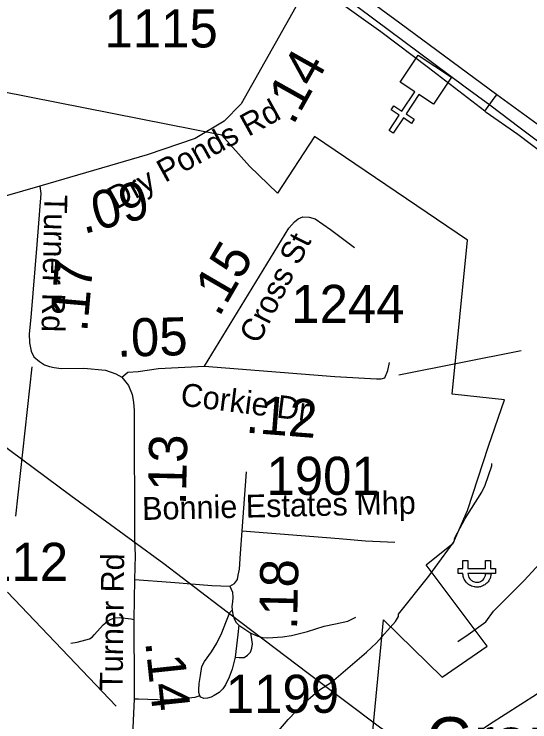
# Model space of a CAD drawing. Extents: x 1159738 to 1321356, y 736314 to 882035.
# Drawn here: x 1273311 to 1275002, y 755538 to 757861 of the extents above; entities that cross this region are included whole.
import ezdxf

# ---------------------------------------------------------------- set-up
doc = ezdxf.new("R2010")
doc.units = 0
for name, color, linetype in [('Exist Boundary Political City Limit New', 7, 'Continuous'), ('Exist Cultural Church CELL', 7, 'Continuous'), ('Exist Cultural Educational Facility Middle Label', 7, 'Continuous'), ('Exist Hydrographic Misc Water Feature', 7, 'Continuous'), ('Exist Railroad Mainline', 7, 'Continuous'), ('Exist Road Non-System Type 51', 7, 'Continuous'), ('Exist Road Primary US Attributed', 7, 'Continuous'), ('Exist Road Secondary Mileage Hundredths English Label', 7, 'Continuous'), ('Exist Road Secondary Type 51 Attributed', 7, 'Continuous'), ('Exist Road Secondary Type 51 Label', 7, 'Continuous'), ('Exist Road Secondary Type 51 Number Label', 7, 'Continuous'), ('Exist Utilities Electrical Power Substation CELL', 7, 'Continuous'), ('Exist Utilities Electrical Transmission Line', 7, 'Continuous'), ('Map Preparation Boundary City Limit Buffer Line', 7, 'Continuous')]:
    doc.layers.add(name, color=color, linetype=linetype)

msp = doc.modelspace()

# ---------------------------------------------------------------- linework, layer by layer
at = {"layer": 'Exist Boundary Political City Limit New'}
msp.add_lwpolyline([(1274481.5, 755451.1), (1274521.9, 755872.3), (1274714.5, 755684.3), (1274861.9, 755786.6), (1274662.2, 756053.1), (1274750.1, 756124.5), (1274797.7, 756231.5), (1274866.6, 756443.3), (1274918.8, 756594.5), (1274747.6, 756613.5), (1274797.5, 757119.5), (1274295.9, 757459.2), (1274174.6, 757273.7), (1274081.9, 757361.7), (1273991.5, 757464), (1272010.1, 757855.7), (1271901.3, 756992.7), (1271608.9, 756928.5)], dxfattribs=at)
at = {"layer": 'Exist Cultural Church CELL'}
msp.add_lwpolyline([(1274685.5, 757565.3), (1274638.1, 757596.8), (1274595.9, 757533.4), (1274622.5, 757515.7), (1274613.6, 757502.4), (1274587, 757520.2), (1274553.7, 757470.1), (1274540.3, 757479), (1274573.7, 757529), (1274547, 757546.8), (1274555.9, 757560.1), (1274582.5, 757542.3), (1274624.7, 757605.7), (1274576.8, 757637.8), (1274635.8, 757726.4), (1274744.5, 757653.9)], close=True, dxfattribs=at)
at = {"layer": 'Exist Hydrographic Misc Water Feature'}
msp.add_lwpolyline([(1274160, 755487.2), (1274209.6, 755545.7), (1274261.4, 755600.2), (1274312.4, 755642.8), (1274351.1, 755667.6), (1274465.9, 755766.3), (1274498.8, 755797.4), (1274560.7, 755867.6), (1274571.1, 755883.3), (1274571.4, 755891.3), (1274670.8, 756016.4), (1274754.1, 756130), (1274756.3, 756141.9), (1274790.1, 756204.9), (1274844.5, 756291.3), (1274855.1, 756315), (1274877, 756378.4), (1274877.2, 756386.4)], dxfattribs=at)
at = {"layer": 'Exist Railroad Mainline'}
msp.add_lwpolyline([(1274294.4, 757992.5), (1274438.5, 757884.3), (1274790.1, 757622.8), (1274871.1, 757562.9), (1274970.6, 757488.2), (1275188, 757324.4), (1275269.6, 757254.7), (1275292.8, 757232.4), (1275355.1, 757167.3), (1275403.2, 757109.9), (1275501.1, 756981.4), (1275557.5, 756901.1), (1275681.6, 756727.1), (1275714.9, 756681.2), (1275850.1, 756492.2), (1275904.4, 756420.6), (1275980.5, 756327.1), (1276054.8, 756250.5), (1276184.8, 756127.4), (1276521.9, 755816.4), (1276790.7, 755569.6), (1276845, 755519), (1276964.6, 755410.8), (1277036.9, 755353.2)], dxfattribs=at)
at = {"layer": 'Exist Road Non-System Type 51'}
msp.add_line((1274058.7, 756165.2), (1274072.7, 756358.9), dxfattribs=at)
for points in [[(1274853.8, 757542.1), (1274797.7, 757585.8), (1274669, 757685.1), (1274513.3, 757803.3), (1274361.3, 757912.7), (1274317.1, 757944.4), (1274278.1, 757964.1)], [(1274853.8, 757542.1), (1274884.9, 757585.2), (1274893.5, 757596.4)], [(1275260.7, 757232.9), (1275240.2, 757250.6), (1275173.1, 757305.8), (1275105.5, 757357.6), (1274962.7, 757466), (1274859.1, 757538.5), (1274853.8, 757542.1)], [(1274766, 755801.6), (1274800, 755824.2), (1274857.3, 755866.5), (1274882.9, 755900.7), (1274916.1, 755935.4), (1274982.9, 756002.2), (1275136.6, 756168.5), (1275298.2, 756346.1), (1275320.4, 756367.1)], [(1274728.2, 755416), (1274734.9, 755430.7), (1274754, 755452.5), (1274869.3, 755530.5), (1275024, 755628.6), (1275238.1, 755773.7), (1275494.7, 755942.8), (1275687.2, 756063.6), (1275875.4, 756171.8), (1275986.2, 756236.7), (1276007.1, 756250.1), (1276017.4, 756259.4)], [(1274018.3, 755983.6), (1274026.4, 755963.4), (1274027.6, 755945.5), (1274026.4, 755932.2), (1274024.7, 755916), (1274025.3, 755905)], [(1273919.5, 755623.7), (1273916.7, 755634.7), (1273916.1, 755642.8), (1273917.8, 755664.2), (1273921.3, 755690.2), (1273925.9, 755719.7), (1273934.6, 755735.9), (1273957.7, 755767.7), (1273975, 755796), (1273991.2, 755830.1), (1274004.5, 755864.2), (1274017.8, 755897), (1274025.3, 755905)], [(1274025.3, 755905), (1274027.6, 755890.5), (1274031.6, 755877.2), (1274038, 755865.1), (1274047.2, 755855.3)], [(1273496, 755795.7), (1273517.7, 755799), (1273545.3, 755807.6), (1273557.7, 755810.9), (1273566.9, 755816.3), (1273574, 755824.4), (1273602.1, 755856.4), (1273616.2, 755868.3), (1273626.5, 755873.7), (1273640, 755879.1), (1273656.3, 755880.2), (1273694.2, 755875.9), (1273702.8, 755873.7)], [(1274086.5, 755828.7), (1274109.6, 755818.8), (1274124.6, 755814.8), (1274142, 755813.1), (1274190.5, 755816.5), (1274220.5, 755821.2), (1274272.5, 755834.5), (1274326.9, 755851.8), (1274365, 755859.3), (1274405.2, 755868), (1274430.7, 755881.3)], [(1274047.2, 755855.3), (1274043.8, 755824.3), (1274035.7, 755750.3)], [(1274047.2, 755855.3), (1274086.5, 755828.7)], [(1274035.7, 755750.3), (1274049, 755748.6), (1274064.6, 755748.6), (1274075.6, 755756.7), (1274085.4, 755766.5), (1274090, 755779.8), (1274091.7, 755793.7), (1274090, 755808.1), (1274086.5, 755828.7)], [(1274035.7, 755750.3), (1274025.3, 755710.4), (1274016, 755684.4), (1274003.9, 755659.5), (1273994.7, 755646.2), (1273983.1, 755634.7), (1273966.9, 755624.3), (1273956.5, 755618.5), (1273944.4, 755615.6), (1273932.8, 755615), (1273923, 755619.1), (1273919.5, 755623.7)], [(1273919.5, 755623.7), (1273902.9, 755617.4), (1273883.2, 755615.1), (1273859.5, 755613.4), (1273811, 755609.3), (1273718.1, 755612.8), (1273704.2, 755612.8)]]:
    msp.add_lwpolyline(points, dxfattribs=at)
at = {"layer": 'Exist Road Primary US Attributed'}
msp.add_lwpolyline([(1276194.4, 756154.4), (1276086.7, 756255.2), (1276045.1, 756298.6), (1275980, 756377), (1275882, 756511.2), (1275825.3, 756588), (1275745.1, 756702.9), (1275697.5, 756764.8), (1275551.9, 756965.3), (1275457.1, 757095.9), (1275376.5, 757201.6), (1275337.2, 757247.9), (1275283.1, 757302.9), (1275224.5, 757353.2), (1275113.7, 757436.5), (1275038.1, 757490.6), (1274893.5, 757596.4), (1274575.7, 757831.2), (1274375.6, 757978.8), (1274315.6, 758022.3)], dxfattribs=at)
at = {"layer": 'Exist Road Secondary Type 51 Attributed'}
for points in [[(1274294.4, 757992.5), (1274278.1, 757964.1), (1274055.2, 757566), (1273999.1, 757509.8), (1273903.9, 757452.3), (1273746.3, 757398.8), (1273395.1, 757296.1)], [(1273395.1, 757296.1), (1273068.4, 757202.1), (1272948.9, 757166.8)], [(1273395.1, 757296.1), (1273398.4, 757271.7), (1273385, 757104.6), (1273365, 756865.2), (1273360.1, 756811.5), (1273360.5, 756782.1), (1273365.9, 756754.9), (1273375.2, 756735.7), (1273393.5, 756720.6), (1273410.4, 756709.9), (1273426, 756704.1), (1273441.5, 756700.6), (1273465.1, 756697.8), (1273539.4, 756698.4), (1273609.8, 756692.2), (1273644.1, 756680.1), (1273664.1, 756669.4)], [(1273934.7, 756704.9), (1274211.2, 757158.2), (1274229.8, 757178.8), (1274242.3, 757189.4), (1274257.6, 757195.6), (1274277.7, 757194.6), (1274297.4, 757189.4), (1274348.6, 757154.4), (1274426.9, 757095)], [(1273934.7, 756704.9), (1274362.1, 756671.1), (1274499.1, 756663.5), (1274514, 756664.2), (1274526.6, 756667.3), (1274536, 756691.1), (1274541.4, 756717.5)], [(1273664.1, 756669.4), (1273683.3, 756685.6), (1273716.9, 756688.4), (1273784.1, 756697.7), (1273934.7, 756704.9)], [(1273664.1, 756669.4), (1273685.8, 756641.5), (1273697.9, 756612.5), (1273701.9, 756587.1), (1273704.5, 756559.6), (1273705.4, 756135.6), (1273707, 756083.8), (1273705.3, 756005.2)], [(1273705.3, 756005.2), (1273824.1, 755995.9), (1273959.2, 755985.4), (1274018.3, 755983.6), (1274032.7, 755991.5), (1274043, 756005.1), (1274045.7, 756019.7), (1274049.5, 756039.2), (1274052.8, 756090.7), (1274058.7, 756165.2), (1274376.7, 756139.7), (1274463.3, 756131.6), (1274559.1, 756127.8)], [(1273705.3, 756005.2), (1273702.8, 755873.7), (1273703.6, 755820.6), (1273704.1, 755703.3), (1273704.6, 755671), (1273704.1, 755635.5), (1273704.2, 755612.8), (1273703.2, 755589.6), (1273700.1, 755518.3), (1273694.7, 755478.6), (1273687.6, 755440.3), (1273662.2, 755364.7), (1273648.9, 755325.7), (1273646.7, 755291.3)]]:
    msp.add_lwpolyline(points, dxfattribs=at)
at = {"layer": 'Exist Road Secondary Type 51 Number Label'}
for p, q in [((1274572.1, 756676.8), (1274973.1, 756757)), ((1273368.9, 756703.6), (1273315.4, 756213.4)), ((1273645.2, 755589.5), (1273288.7, 755963.8))]:
    msp.add_line(p, q, dxfattribs=at)
at = {"layer": 'Exist Utilities Electrical Power Substation CELL'}
msp.add_lwpolyline([(1274766.3, 756041.3), (1274782.3, 756041.3), (1274782.3, 756067.7), (1274798.6, 756067.7), (1274798.6, 756041.3), (1274856.7, 756041.3), (1274856.7, 756067.7), (1274872.9, 756067.7), (1274872.9, 756041.3), (1274889, 756041.3), (1274889, 756025.3), (1274872.9, 756025.3), (1274856.7, 756025.3), (1274798.6, 756025.3), (1274799.1, 756020.3), (1274800.1, 756015.9), (1274802.1, 756011.3), (1274805.1, 756006.9), (1274809, 756002.9), (1274811.1, 756001.3), (1274813.6, 755999.9), (1274816.7, 755998.2), (1274820.1, 755997.1), (1274824.1, 755996.3), (1274827.1, 755996.1), (1274830.5, 755996.2), (1274834.4, 755996.8), (1274837.9, 755997.8), (1274840.3, 755998.8), (1274843, 756000.3), (1274845.8, 756002.2), (1274848.4, 756004.5), (1274850.6, 756007), (1274852.3, 756009.3), (1274853.4, 756011.3), (1274854.6, 756013.5), (1274855.7, 756016.4), (1274856.1, 756018.3), (1274856.8, 756021.3), (1274856.9, 756023.6), (1274857.1, 756025.3), (1274874.8, 756025.3), (1274874.5, 756022.5), (1274874.2, 756020.3), (1274873.8, 756017.6), (1274873.1, 756014.9), (1274872.3, 756011.8), (1274871.4, 756009.2), (1274870.4, 756006.6), (1274868.9, 756003.7), (1274867, 756000.8), (1274864.9, 755997.8), (1274862.8, 755995.3), (1274860.6, 755993.1), (1274857.7, 755990.4), (1274854.5, 755988.1), (1274851.1, 755986), (1274847.5, 755984.2), (1274844.7, 755983), (1274842.2, 755982.2), (1274839.6, 755981.5), (1274836.5, 755980.8), (1274833.4, 755980.4), (1274830.6, 755980.1), (1274827, 755980.1), (1274824.5, 755980.3), (1274821.7, 755980.6), (1274818.8, 755981.2), (1274814.8, 755982.1), (1274810.7, 755983.6), (1274807.1, 755985.3), (1274804.1, 755987), (1274800.7, 755989.2), (1274798.1, 755991.4), (1274796.6, 755992.7), (1274794.6, 755994.7), (1274793, 755996.6), (1274790.7, 755999.3), (1274788.5, 756002.8), (1274786.9, 756005.8), (1274785.6, 756008.6), (1274784.7, 756011.2), (1274783.4, 756015.4), (1274782.7, 756019), (1274782.3, 756022.1), (1274782.1, 756025.3), (1274766.3, 756025.3)], close=True, dxfattribs=at)
at = {"layer": 'Exist Utilities Electrical Transmission Line'}
msp.add_lwpolyline([(1271643.6, 757658.1), (1271884.5, 757481.5), (1272100.6, 757324.1), (1272362.9, 757127.6), (1272636.6, 756926.8), (1272961.2, 756680.1), (1273214.9, 756490.2), (1273496.7, 756281.2), (1273801.2, 756057.6), (1273981.6, 755919.4), (1274274.9, 755698), (1274509.1, 755521.7), (1274592.5, 755464.8), (1274635.8, 755239.2), (1274685, 755019.8), (1274724.5, 754853.4), (1274978.3, 754774.1), (1275053.6, 754586.1), (1275158.7, 754355.6), (1275343, 753976.3), (1275450.1, 753710.3), (1275612.4, 753375.8), (1275696.2, 753198)], dxfattribs=at)
at = {"layer": 'Map Preparation Boundary City Limit Buffer Line'}
msp.add_lwpolyline([(1274481.5, 755451.1), (1274521.9, 755872.3), (1274714.5, 755684.3), (1274861.9, 755786.6), (1274662.2, 756053.1), (1274750.1, 756124.5), (1274797.7, 756231.5), (1274866.6, 756443.3), (1274918.8, 756594.5), (1274747.6, 756613.5), (1274797.5, 757119.5), (1274295.9, 757459.2), (1274174.6, 757273.7), (1274081.9, 757361.7), (1273991.5, 757464), (1272010.1, 757855.7), (1271901.3, 756992.7), (1271608.9, 756928.5)], dxfattribs=at)

# ---------------------------------------------------------------- texts
at = {"layer": 'Exist Cultural Educational Facility Middle Label'}
msp.add_text('Granite Falls', height=150, dxfattribs=at).set_placement((1274662.1, 755403.3))
at = {"layer": 'Exist Road Secondary Mileage Hundredths English Label'}
for s, rotation, p in [('.14', 60.7604, (1274225.1, 757493.5)), ('.09', 14.6255, (1273538.1, 757138.7)), ('.15', 59.8202, (1273982, 756863.4)), ('.17', 84.8785, (1273549.7, 756815.1)), ('.05', 1.5021, (1273648.6, 756735.8)), ('.12', 355.5516, (1274067.5, 756487.6)), ('.13', 88.7301, (1273873.7, 756247.9)), ('.18', 88.8331, (1274238.3, 755838.8)), ('.14', 276.066, (1273740.3, 755800))]:
    msp.add_text(s, height=125, rotation=rotation, dxfattribs=at).set_placement(p)
at = {"layer": 'Exist Road Secondary Type 51 Label'}
for s, rotation, p in [('Dry Ponds Rd', 28.8923, (1273644.3, 757217.9)), ('Turner Rd', 268.7475, (1273410.3, 757269.1)), ('Cross St', 63.0129, (1274112.2, 756774.9)), ('Corkie Dr', 352.8205, (1273853.6, 756576.7)), ('Bonnie Estates Mhp', 1.3215, (1273730.9, 756200.3)), ('Turner Rd', 89.3085, (1273666.1, 755639))]:
    msp.add_text(s, height=75, rotation=rotation, dxfattribs=at).set_placement(p)
at = {"layer": 'Exist Road Secondary Type 51 Number Label'}
for s, p in [('1115', (1273606.6, 757751.6)), ('1244', (1274219.4, 756847.3)), ('1901', (1274137.9, 756283)), ('1112', (1273115.8, 756000.6)), ('1199', (1274004.6, 755567.4))]:
    msp.add_text(s, height=125, dxfattribs=at).set_placement(p)

doc.saveas('drawing.dxf')
